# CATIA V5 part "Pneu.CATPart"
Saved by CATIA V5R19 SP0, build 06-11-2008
Part number: Pneu
Material "Aucun"
Material "Bandes N&B Oy": density 2000 kg/m3
Bounding box of the stored display mesh (mm): x -97.5 to 97.5, y -303.65 to 303.65, z -303.65 to 303.65
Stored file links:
  G:\EU_thinkMotion\CFAO_2010\MMS_groupe3\MMS_groupe3\A reprendre\bblot\BLOT\Pneu.CATPart
  C:\Program Files\Dassault Systemes\B19\intel_a\startup\materials\French\Catalog.CATMaterial
  J:\IFMA\2ème Année\Semestre 3\Outils de l'ingénieur\CFAO - CFAO et usine numérique\TP\ThinkMotion\BLOT_Benoit\Amortisseur_mouvement.CATProduct
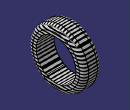
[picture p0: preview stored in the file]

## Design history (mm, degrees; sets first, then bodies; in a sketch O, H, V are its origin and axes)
Parameters
  Largeur = 195 mm
  Hauteur = 87.75 mm {= (Largeur*Hauteur_pourcentage)/100}
  Hauteur_pourcentage = 45
  `Diamètre jante` = 431.8 mm {= `Diamètre jante (en pouce)` *25.4}
  `Diamètre jante (en pouce)` = 17 mm
Set1
  Point1: type OnPlane, Support zx-plane, H 0, V 303.65 {= Hauteur +`Diamètre jante` /2}, Direction (-1, 0, 0)
  Plane1: type Tangent, Support face of Shaft1 from Sketch2.L1, RefPoint Point1
  Sketch1 on Plane1, origin (0, 0, 303.65), H (1, 0, 0), V (0, -1, 0)
    spline S1 through (0, 0) (25.0883, -18.6639) (36.0976, -33.8017) (43.5289, -47.5634) (45.1803, -32.4256) (34.7215, -10.9574) (0, 0)
    point P1 (0, 0)
    point P2 (0, 0)
    coincidence: P1 O, P2 O
  Develop1
  Point2: (0, 0, 0)
  CircPattern1: of Develop1, instances 25, angular step 15, axis from yz-plane
Body1 (main body), material "Bandes N&B Oy"
  Sketch2 on zx-plane, origin (0, 0, 0), H (-1, 0, 0), V (0, 0, 1)
    line L1 (-97.5, 303.65) -> (97.5, 303.65)
    line L2 (97.5, 303.65) -> (97.5, 215.9)
    line L3 (97.5, 215.9) -> (-97.5, 215.9)
    line L4 (-97.5, 215.9) -> (-97.5, 303.65)
    construction line L5 (0, 0) -> (0, 303.65)
    point P5 (0, 0)
    point P6 (0, 303.65)
    reference intersected line E1 through (0, 0) direction (-1, 0) from xy-plane
    axis line L6 (0, 0) -> (457.4983, 0)
    distance L3 E1 = 215.9 {= `Diamètre jante` /2}
    length L1 = 195 {= Largeur}
    length L2 = 87.75 {= Hauteur}
    horizontal: L1 H, L3 H, L6 H
    vertical: L2 V, L4 V, L5 V
    coincidence: P5 H, P5 O
    midpoint: P6 L1
  Shaft1: profile Sketch2, axis Sketch2.L6, angle 360
  Fillet1: radius 50, on edge [face of Shaft1 from Sketch2.L4 | face of Shaft1 from Sketch2.L1]; edge [face of Shaft1 from Sketch2.L1 | face of Shaft1 from Sketch2.L2]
